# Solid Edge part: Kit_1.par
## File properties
Sűrűség: 0,000 kg/m^3
Pontosság: 0,990
Author: bmolnar
Last saved by: bmolnar
Revision: 77
Username: bmolnar
Dokumentum tartalom típus: 0
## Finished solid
Body 1: solid body, 44 faces, 61 edges, 51 vertices.
  Faces by surface: cylinder 15, cone 13, plane 12, torus 4
  Edges by curve: circle 47, line 14
Bounding box of the edges (mm; curved faces can reach further): 85.500 x 85.350 x 6.900, from (-42.75, -40.85, 88.15) to (42.75, 44.5, 95.05).
Cylindrical faces by radius (mm): R1.5 x2, R3 x4, R10.3 x1, R10.95 x1, R11.5 x1, R12.4 x1, R12.5 x1, R31 x1, R37.5 x1, R40.85 x1, R42.75 x1
Conical faces (half-angle, radius in mm at the cone's reference point): 3 deg R12.45 x1, 7 deg R11.7695 x1, 14 deg R10.15 x1, 14 deg R10.557 x1, 17 deg R10.15 x1, 23 deg R10.9211 x1, 42.5 deg R10.137 x1, 45 deg R11.2 x1, 45 deg R11.6 x1, 45 deg R30.75 x1, 84 deg R10.512 x1, 85 deg R12.1625 x1, 87 deg R10.2157 x1
Toroidal faces (ring radius, tube radius in mm): R10.9008 r0.225 x1, R11.3914 r0.325 x1, R12.2 r0.2 x1, R31.8 r0.8 x1
Planar faces by outward normal: +z 7, -z 3, oblique 2
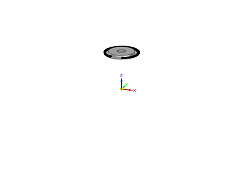
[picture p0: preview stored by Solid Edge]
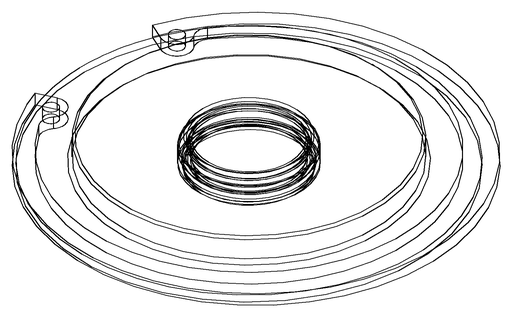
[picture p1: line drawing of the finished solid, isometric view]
